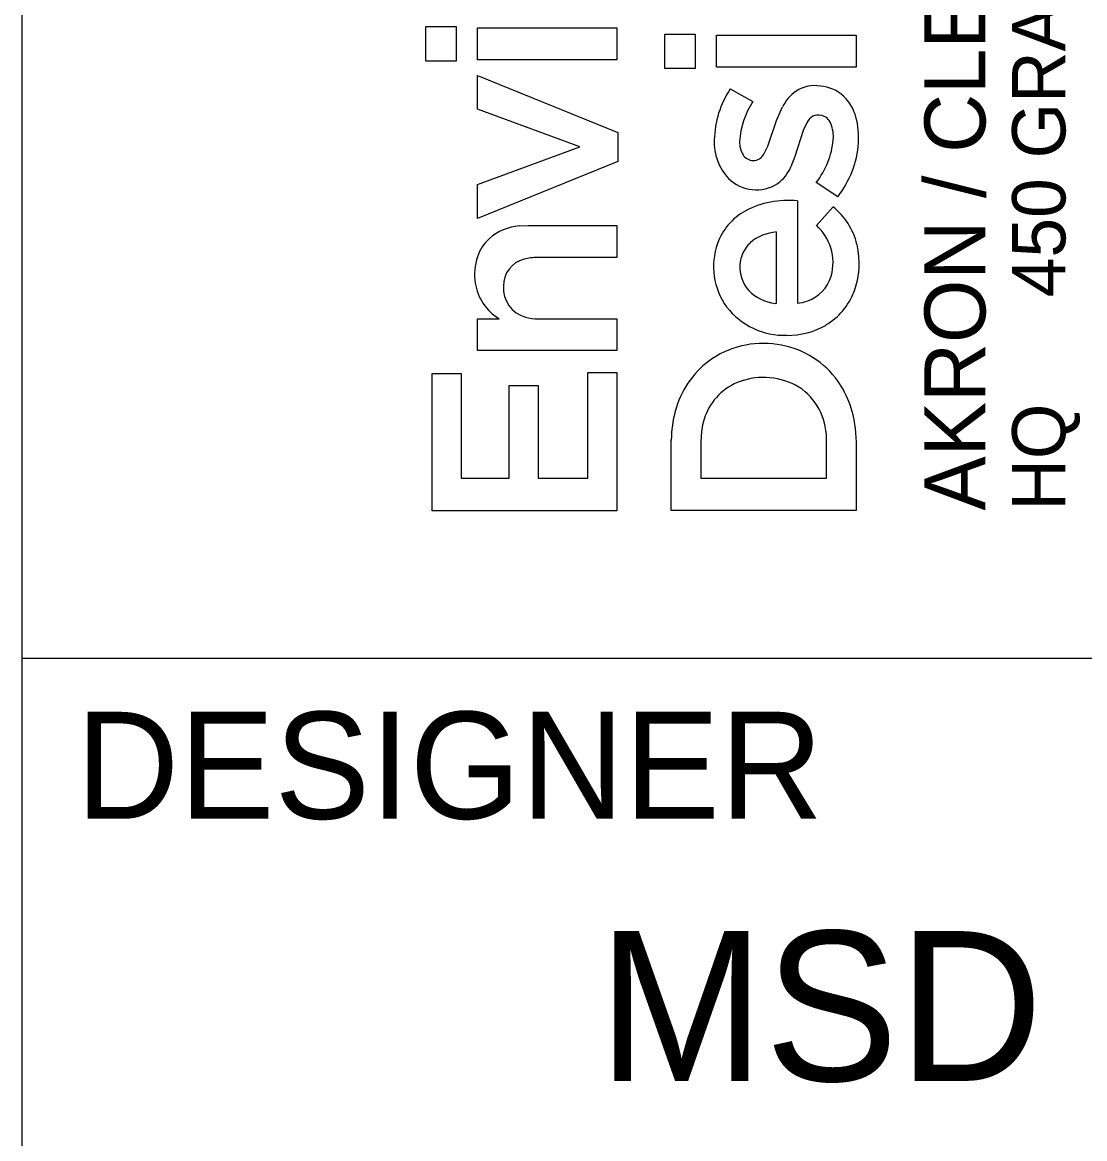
# Model space of a CAD drawing. Extents: x -4.4 to 34, y -1.2 to 22.
# Drawn here: x 32 to 32.993, y 2.551 to 3.594 of the extents above; entities that cross this region are included whole.
import ezdxf

# ---------------------------------------------------------------- set-up
doc = ezdxf.new("R2010")
doc.units = 0
doc.layers.add('SH_Border', color=7, linetype='Continuous')
doc.layers.add('SH_Cut_Line', color=7, linetype='Continuous')

msp = doc.modelspace()

# ---------------------------------------------------------------- linework, layer by layer
at = {"layer": 'SH_Border'}
for p, q in [((32, 0.5), (32, 21.5)), ((32, 3), (33.5, 3))]:
    msp.add_line(p, q, dxfattribs=at)
at = {"layer": 'SH_Cut_Line'}
for p, q in [((32.3771, 3.5582), (32.3771, 3.5903)), ((32.3771, 3.5903), (32.4054, 3.5903)), ((32.4054, 3.5903), (32.4054, 3.5582)), ((32.4254, 3.5594), (32.4254, 3.5893)), ((32.4254, 3.5893), (32.5557, 3.5893)), ((32.5557, 3.5893), (32.5557, 3.5594)), ((32.6005, 3.5511), (32.6005, 3.5832)), ((32.6005, 3.5832), (32.6289, 3.5832)), ((32.6289, 3.5832), (32.6289, 3.5511)), ((32.6489, 3.5523), (32.6489, 3.5822)), ((32.6489, 3.5822), (32.7792, 3.5822)), ((32.7792, 3.5822), (32.7792, 3.5523)), ((32.4054, 3.5582), (32.3771, 3.5582)), ((32.5557, 3.5594), (32.4254, 3.5594)), ((32.6289, 3.5511), (32.6005, 3.5511)), ((32.7792, 3.5523), (32.6489, 3.5523)), ((32.4254, 3.5133), (32.4254, 3.5446)), ((32.4254, 3.5446), (32.5567, 3.4913)), ((32.6615, 3.5321), (32.6827, 3.5203)), ((32.5212, 3.478), (32.4254, 3.5133)), ((32.7048, 3.5026), (32.7104, 3.5153)), ((32.6967, 3.4787), (32.7048, 3.5026)), ((32.7334, 3.501), (32.7298, 3.4933)), ((32.5567, 3.4913), (32.5567, 3.4644)), ((32.7298, 3.4933), (32.7221, 3.4688)), ((32.4254, 3.4429), (32.5212, 3.478)), ((32.693, 3.4712), (32.6967, 3.4787)), ((32.5567, 3.4644), (32.4254, 3.4109)), ((32.7221, 3.4688), (32.7182, 3.4592)), ((32.7621, 3.4314), (32.742, 3.4447)), ((32.4254, 3.4109), (32.4254, 3.4429)), ((32.7245, 3.4275), (32.7246, 3.3319)), ((32.7423, 3.4046), (32.7577, 3.422)), ((32.4644, 3.404), (32.4729, 3.4044)), ((32.4729, 3.4044), (32.5557, 3.4044)), ((32.5557, 3.4044), (32.5557, 3.3746)), ((32.7049, 3.3318), (32.7049, 3.3983)), ((32.5557, 3.3746), (32.4814, 3.3746)), ((32.7036, 3.3317), (32.7049, 3.3318)), ((32.4254, 3.2875), (32.4254, 3.3173)), ((32.4254, 3.3173), (32.4455, 3.3173)), ((32.4822, 3.3173), (32.5557, 3.3173)), ((32.5557, 3.3173), (32.5557, 3.2876)), ((32.5557, 3.2876), (32.4254, 3.2875)), ((32.383, 3.1379), (32.383, 3.266)), ((32.383, 3.266), (32.4101, 3.266)), ((32.4101, 3.266), (32.4101, 3.1683)), ((32.5286, 3.1683), (32.5286, 3.2672)), ((32.5286, 3.2672), (32.5557, 3.2672)), ((32.5557, 3.2672), (32.5557, 3.1379)), ((32.455, 3.1683), (32.455, 3.2549)), ((32.455, 3.2549), (32.4822, 3.2549)), ((32.4822, 3.2549), (32.4822, 3.1683)), ((32.7785, 3.215), (32.7792, 3.2021)), ((32.6064, 3.138), (32.6064, 3.204)), ((32.6347, 3.2118), (32.6341, 3.2023)), ((32.6341, 3.2023), (32.6341, 3.1684)), ((32.7515, 3.1683), (32.7515, 3.2024)), ((32.7792, 3.2021), (32.7792, 3.138)), ((32.4101, 3.1683), (32.455, 3.1683)), ((32.4822, 3.1683), (32.5286, 3.1683)), ((32.6341, 3.1684), (32.7515, 3.1683)), ((32.5557, 3.1379), (32.383, 3.1379)), ((32.7792, 3.138), (32.6064, 3.138))]:
    msp.add_line(p, q, dxfattribs=at)
for points in [[(32.3771, 3.5582), (32.3771, 3.5903), (32.4054, 3.5903), (32.4054, 3.5582)], [(32.4254, 3.5594), (32.4254, 3.5893), (32.5557, 3.5893), (32.5557, 3.5594)], [(32.6005, 3.5511), (32.6005, 3.5832), (32.6289, 3.5832), (32.6289, 3.5511)], [(32.6489, 3.5523), (32.6489, 3.5822), (32.7792, 3.5822), (32.7792, 3.5523)], [(32.4254, 3.4109), (32.4254, 3.4429), (32.5212, 3.478), (32.4254, 3.5133), (32.4254, 3.5446), (32.5567, 3.4913), (32.5567, 3.4644)], [(32.383, 3.1379), (32.383, 3.266), (32.4101, 3.266), (32.4101, 3.1683), (32.455, 3.1683), (32.455, 3.2549), (32.4822, 3.2549), (32.4822, 3.1683), (32.5286, 3.1683), (32.5286, 3.2672), (32.5557, 3.2672), (32.5557, 3.1379)]]:
    msp.add_lwpolyline(points, close=True, dxfattribs=at)
for points in [[(32.6615, 3.5321), (32.6827, 3.5203)], [(32.693, 3.4712), (32.6967, 3.4787), (32.7048, 3.5026), (32.7104, 3.5153)], [(32.7334, 3.501), (32.7298, 3.4933), (32.7221, 3.4688), (32.7182, 3.4592)], [(32.7621, 3.4314), (32.742, 3.4447)], [(32.7245, 3.4275), (32.7246, 3.3319)], [(32.7423, 3.4046), (32.7577, 3.422)], [(32.4644, 3.404), (32.4729, 3.4044), (32.5557, 3.4044), (32.5557, 3.3746), (32.4814, 3.3746)], [(32.7036, 3.3317), (32.7049, 3.3318), (32.7049, 3.3983)], [(32.4254, 3.2875), (32.4254, 3.3173), (32.4455, 3.3173)], [(32.4822, 3.3173), (32.5557, 3.3173), (32.5557, 3.2876), (32.4254, 3.2875)], [(32.7785, 3.215), (32.7792, 3.2021), (32.7792, 3.138), (32.6064, 3.138)], [(32.6064, 3.138), (32.6064, 3.204)], [(32.6347, 3.2118), (32.6341, 3.2023), (32.6341, 3.1684), (32.7515, 3.1683), (32.7515, 3.2024)]]:
    msp.add_lwpolyline(points, dxfattribs=at)
for centre, radius, start, end in [((32.7364, 3.4826), 0.0897, 146.531, 178.7571), ((32.7364, 3.4826), 0.0897, 146.531, 178.7571), ((32.7466, 3.4971), 0.0405, 125.5118, 153.4159), ((32.7466, 3.4971), 0.0405, 125.5118, 153.4159), ((32.7406, 3.5026), 0.0326, 80.1719, 122.5197), ((32.7406, 3.5026), 0.0326, 80.1719, 122.5197), ((32.7428, 3.4982), 0.0367, 47.7934, 84.6892), ((32.7428, 3.4982), 0.0367, 47.7934, 84.6892), ((32.7452, 3.4789), 0.0749, 146.5112, 176.9101), ((32.7452, 3.4789), 0.0749, 146.5112, 176.9101), ((32.7379, 3.4946), 0.0427, 14.9966, 46.2063), ((32.7379, 3.4946), 0.0427, 14.9966, 46.2063), ((32.7438, 3.4963), 0.0114, 76.6609, 155.7053), ((32.7438, 3.4963), 0.0114, 76.6609, 155.7053), ((32.744, 3.4951), 0.0126, 21.5098, 78.5262), ((32.744, 3.4951), 0.0126, 21.5098, 78.5262), ((32.7104, 3.4867), 0.0712, 355.8306, 15.3914), ((32.7104, 3.4867), 0.0712, 355.8306, 15.3914), ((32.7259, 3.4877), 0.0321, 354.5726, 22.068), ((32.7259, 3.4877), 0.0321, 354.5726, 22.068), ((32.6967, 3.4824), 0.0501, 177.5366, 222.7932), ((32.6967, 3.4824), 0.0501, 177.5366, 222.7932), ((32.6931, 3.4823), 0.0228, 178.4747, 211.0868), ((32.6931, 3.4823), 0.0228, 178.4747, 211.0868), ((32.6825, 3.4915), 0.0757, 321.811, 354.7969), ((32.6825, 3.4915), 0.0757, 321.811, 354.7969), ((32.6895, 3.4882), 0.0922, 321.9777, 355.8738), ((32.6895, 3.4882), 0.0922, 321.9777, 355.8738), ((32.6833, 3.4767), 0.0115, 212.2368, 268.3777), ((32.6833, 3.4767), 0.0115, 212.2368, 268.3777), ((32.6834, 3.4759), 0.0107, 267.716, 333.7337), ((32.6834, 3.4759), 0.0107, 267.716, 333.7337), ((32.681, 3.4758), 0.0408, 308.0877, 335.9874), ((32.681, 3.4758), 0.0408, 308.0877, 335.9874), ((32.686, 3.4753), 0.0375, 225.9854, 302.4797), ((32.686, 3.4753), 0.0375, 225.9854, 302.4797), ((32.7152, 3.3441), 0.0838, 83.615, 118.2876), ((32.7152, 3.3441), 0.0838, 83.615, 118.2876), ((32.7024, 3.3691), 0.0558, 118.8308, 160.6244), ((32.7024, 3.3691), 0.0558, 118.8308, 160.6244), ((32.7174, 3.3717), 0.0644, 13.5336, 51.3615), ((32.7174, 3.3717), 0.0644, 13.5336, 51.3615), ((32.4687, 3.3543), 0.0499, 94.9696, 130.2225), ((32.4687, 3.3543), 0.0499, 94.9696, 130.2225), ((32.7038, 3.3656), 0.0549, 19.0357, 45.4406), ((32.7038, 3.3656), 0.0549, 19.0357, 45.4406), ((32.4635, 3.3626), 0.0402, 132.2219, 161.6818), ((32.4635, 3.3626), 0.0402, 132.2219, 161.6818), ((32.7079, 3.3561), 0.0424, 94.008, 130.8817), ((32.7079, 3.3561), 0.0424, 94.008, 130.8817), ((32.7104, 3.3661), 0.0644, 160.5201, 215.7831), ((32.7104, 3.3661), 0.0644, 160.5201, 215.7831), ((32.7005, 3.3663), 0.0298, 132.9851, 177.179), ((32.7005, 3.3663), 0.0298, 132.9851, 177.179), ((32.7107, 3.3697), 0.047, 344.6059, 17.007), ((32.7107, 3.3697), 0.047, 344.6059, 17.007), ((32.7064, 3.3692), 0.0758, 339.3542, 13.3785), ((32.7064, 3.3692), 0.0758, 339.3542, 13.3785), ((32.4787, 3.3582), 0.056, 162.2736, 187.7919), ((32.4787, 3.3582), 0.056, 162.2736, 187.7919), ((32.4748, 3.3487), 0.025, 103.6865, 182.2187), ((32.4748, 3.3487), 0.025, 103.6865, 182.2187), ((32.4811, 3.3286), 0.046, 89.6049, 105.3284), ((32.4811, 3.3286), 0.046, 89.6049, 105.3284), ((32.7017, 3.365), 0.0311, 175.0013, 223.283), ((32.7017, 3.365), 0.0311, 175.0013, 223.283), ((32.4703, 3.358), 0.0476, 188.962, 238.7037), ((32.4703, 3.358), 0.0476, 188.962, 238.7037), ((32.7224, 3.3671), 0.035, 288.0077, 343.5508), ((32.7224, 3.3671), 0.035, 288.0077, 343.5508), ((32.4773, 3.3456), 0.0276, 175.5854, 255.1439), ((32.4773, 3.3456), 0.0276, 175.5854, 255.1439), ((32.7089, 3.3736), 0.0423, 225.0619, 262.7974), ((32.7089, 3.3736), 0.0423, 225.0619, 262.7974), ((32.7189, 3.3652), 0.0626, 300.9427, 338.7323), ((32.7189, 3.3652), 0.0626, 300.9427, 338.7323), ((32.7125, 3.3705), 0.0687, 217.7452, 271.6543), ((32.7125, 3.3705), 0.0687, 217.7452, 271.6543), ((32.7247, 3.3522), 0.0202, 269.7003, 294.8711), ((32.7247, 3.3522), 0.0202, 269.7003, 294.8711), ((32.4818, 3.3595), 0.0422, 254.0916, 270.5284), ((32.4818, 3.3595), 0.0422, 254.0916, 270.5284), ((32.7155, 3.3724), 0.0706, 269.2048, 300.3341), ((32.7155, 3.3724), 0.0706, 269.2048, 300.3341), ((32.6923, 3.2079), 0.0864, 81.194, 125.9984), ((32.6923, 3.2079), 0.0864, 81.194, 125.9984), ((32.6946, 3.2113), 0.0827, 37.8521, 82.402), ((32.6946, 3.2113), 0.0827, 37.8521, 82.402), ((32.6939, 3.2089), 0.0865, 127.2362, 165.148), ((32.6939, 3.2089), 0.0865, 127.2362, 165.148), ((32.6889, 3.2078), 0.054, 106.1881, 157.3861), ((32.6889, 3.2078), 0.054, 106.1881, 157.3861), ((32.6928, 3.1986), 0.0639, 55.6727, 107.2093), ((32.6928, 3.1986), 0.0639, 55.6727, 107.2093), ((32.6859, 3.2057), 0.0931, 5.7333, 37.304), ((32.6859, 3.2057), 0.0931, 5.7333, 37.304), ((32.6929, 3.205), 0.0587, 357.4662, 52.2665), ((32.6929, 3.205), 0.0587, 357.4662, 52.2665), ((32.7143, 3.2028), 0.1078, 164.7861, 179.3704), ((32.7143, 3.2028), 0.1078, 164.7861, 179.3704), ((32.6983, 3.2039), 0.0641, 157.3571, 172.9275), ((32.6983, 3.2039), 0.0641, 157.3571, 172.9275)]:
    msp.add_arc(centre, radius, start, end, dxfattribs=at)

# ---------------------------------------------------------------- texts
for s, height, p in [('450 GRANT ST., AKRON, OH  44311', 0.049846, (32.9749, 3.3374)), ('AKRON / CLEVELAND / COLUMBUS', 0.056969, (32.9001, 3.138)), ('HQ ', 0.04985, (32.9749, 3.138))]:
    msp.add_text(s, height=height, rotation=90, dxfattribs=at).set_placement(p)
for s, height, p in [('DESIGNER', 0.1, (32.05, 2.85)), ('MSD', 0.14, (32.5379, 2.605))]:
    msp.add_text(s, height=height, dxfattribs=at).set_placement(p)

doc.saveas('drawing.dxf')
